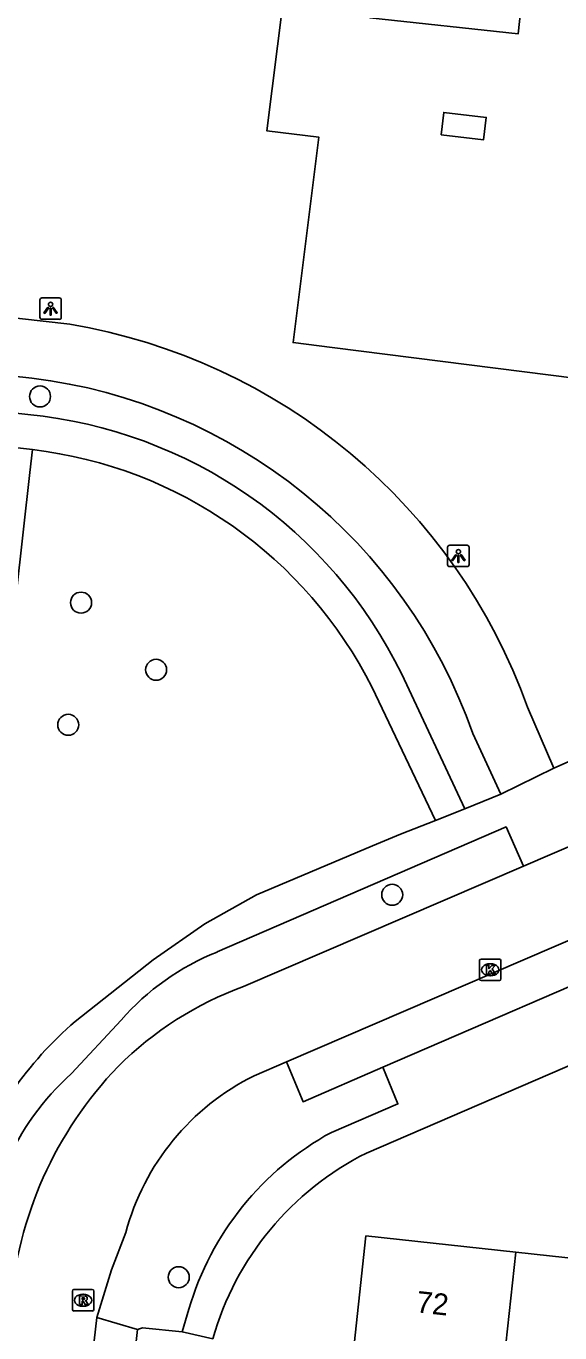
# Model space of a CAD drawing. Extents: x 162026 to 163499, y 387297 to 388169.
# Drawn here: x 162177.7 to 162202.5, y 387793.2 to 387854 of the extents above; entities that cross this region are included whole.
import ezdxf

# ---------------------------------------------------------------- set-up
doc = ezdxf.new("R2010")
doc.units = 0
for name, color, linetype in [('IMGEO_Boom', 7, 'Continuous'), ('IMGEO_Fietspad_gesloten', 7, 'Continuous'), ('IMGEO_Kolk', 7, 'Continuous'), ('IMGEO_Lichtpunt', 7, 'Continuous'), ('IMGEO_Loofbos', 7, 'Continuous'), ('IMGEO_Pand', 7, 'Continuous'), ('IMGEO_Pand_nummerreeks', 7, 'Continuous'), ('IMGEO_Parkeervlak_open', 7, 'Continuous'), ('IMGEO_Rijbaan_lokaal_open', 7, 'Continuous'), ('IMGEO_Rioolput', 7, 'Continuous'), ('IMGEO_Voetpad_open', 7, 'Continuous')]:
    doc.layers.add(name, color=color, linetype=linetype)

msp = doc.modelspace()

# ---------------------------------------------------------------- linework, layer by layer
at = {"layer": 'IMGEO_Boom'}
for centre in [(162178.326, 387836.8), (162180.234, 387827.201), (162183.726, 387824.075), (162179.638, 387821.513), (162194.71, 387813.598), (162184.778, 387795.79)]:
    msp.add_circle(centre, 0.489, dxfattribs=at)
at = {"layer": 'IMGEO_Fietspad_gesloten'}
for points in [[(162177.938, 387837.659), (162144.47, 387841.312)], [(162179.708, 387840.17), (162175.011, 387840.691)], [(162202.235, 387819.498), (162201.008, 387822.336)], [(162199.757, 387818.285), (162198.454, 387821.109)], [(162199.757, 387818.285), (162202.235, 387819.498)]]:
    msp.add_lwpolyline(points, dxfattribs=at)
for centre, radius, start, end in [((162175.123, 387813.057), 27.498, 19.72143, 80.40124), ((162174.885, 387812.883), 24.963, 19.23986, 82.97477)]:
    msp.add_arc(centre, radius, start, end, dxfattribs=at)
at = {"layer": 'IMGEO_Kolk'}
for p, q in [((162198.768, 387809.68), (162198.768, 387810.532)), ((162198.843, 387810.606), (162199.695, 387810.606)), ((162199.256, 387810.386), (162199.281, 387810.386)), ((162199.769, 387810.532), (162199.769, 387809.68)), ((162199.279, 387809.826), (162199.254, 387809.826)), ((162199.695, 387809.606), (162198.843, 387809.606))]:
    msp.add_line(p, q, dxfattribs=at)
for points in [[(162198.768, 387809.68), (162198.768, 387810.532)], [(162198.843, 387810.606), (162199.695, 387810.606)], [(162199.089, 387810.306), (162199.212, 387810.306), (162199.212, 387810.155), (162199.342, 387810.306), (162199.506, 387810.306), (162199.36, 387810.155), (162199.513, 387809.906), (162199.361, 387809.906), (162199.276, 387810.07), (162199.212, 387810.003), (162199.212, 387809.906), (162199.089, 387809.906), (162199.089, 387810.306)], [(162199.769, 387810.532), (162199.769, 387809.68)], [(162199.695, 387809.606), (162198.843, 387809.606)]]:
    msp.add_lwpolyline(points, dxfattribs=at)
for centre, start, end in [((162198.845, 387810.53), 91.55205, 178.44795), ((162198.845, 387810.53), 91.55205, 178.44795), ((162199.693, 387810.53), 1.55205, 88.44795), ((162199.693, 387810.53), 1.55205, 88.44795), ((162198.845, 387809.682), 181.55205, 268.44795), ((162198.845, 387809.682), 181.55205, 268.44795), ((162199.693, 387809.682), 271.55205, 358.44795), ((162199.693, 387809.682), 271.55205, 358.44795)]:
    msp.add_arc(centre, 0.0765, start, end, dxfattribs=at)
for centre, major_axis, ratio, start_param, end_param in [((162199.255, 387810.106), (-0.387, 0.002), 0.722429, 4.712389, 7.853982), ((162199.28, 387810.106), (-0.39, 0.002), 0.717154, 1.570796, 4.712389)]:
    msp.add_ellipse(centre, major_axis=major_axis, ratio=ratio, start_param=start_param, end_param=end_param, dxfattribs=at)
at = {"layer": 'IMGEO_Lichtpunt'}
for p, q in [((162179.222, 387841.389), (162178.414, 387841.389)), ((162179.222, 387841.389), (162178.414, 387841.389)), ((162178.32, 387841.294), (162178.32, 387840.487)), ((162178.32, 387841.294), (162178.32, 387840.487)), ((162179.316, 387840.487), (162179.316, 387841.294)), ((162179.316, 387840.487), (162179.316, 387841.294)), ((162178.414, 387840.393), (162179.222, 387840.393)), ((162178.414, 387840.393), (162179.222, 387840.393)), ((162197.29, 387829.778), (162197.29, 387828.971)), ((162197.29, 387829.778), (162197.29, 387828.971)), ((162198.192, 387829.873), (162197.384, 387829.873)), ((162198.192, 387829.873), (162197.384, 387829.873)), ((162198.286, 387828.971), (162198.286, 387829.778)), ((162198.286, 387828.971), (162198.286, 387829.778)), ((162197.384, 387828.877), (162198.192, 387828.877)), ((162197.384, 387828.877), (162198.192, 387828.877))]:
    msp.add_line(p, q, dxfattribs=at)
for points in [[(162178.694, 387840.958), (162178.733, 387840.93), (162178.545, 387840.668), (162178.507, 387840.695), (162178.694, 387840.958)], [(162178.796, 387840.91), (162178.843, 387840.91), (162178.843, 387840.588), (162178.796, 387840.588), (162178.796, 387840.91)], [(162178.906, 387840.93), (162178.944, 387840.957), (162179.131, 387840.695), (162179.092, 387840.667), (162178.906, 387840.93)], [(162197.664, 387829.442), (162197.703, 387829.414), (162197.515, 387829.152), (162197.477, 387829.179), (162197.664, 387829.442)], [(162197.766, 387829.394), (162197.813, 387829.394), (162197.813, 387829.072), (162197.766, 387829.072), (162197.766, 387829.394)], [(162197.876, 387829.414), (162197.914, 387829.441), (162198.101, 387829.179), (162198.062, 387829.151), (162197.876, 387829.414)]]:
    msp.add_lwpolyline(points, dxfattribs=at)
for centre in [(162178.819, 387841.092), (162197.789, 387829.576)]:
    msp.add_circle(centre, 0.0994, dxfattribs=at)
for centre, start, end in [((162178.414, 387841.294), 90, 180), ((162178.414, 387841.294), 90, 180), ((162179.222, 387841.294), 0, 90), ((162179.222, 387841.294), 0, 90), ((162178.414, 387840.487), 180, 270), ((162178.414, 387840.487), 180, 270), ((162179.222, 387840.487), 270, 0), ((162179.222, 387840.487), 270, 360), ((162197.384, 387829.778), 90, 180), ((162197.384, 387829.778), 90, 180), ((162198.192, 387829.778), 0, 90), ((162198.192, 387829.778), 0, 90), ((162197.384, 387828.971), 180, 270), ((162197.384, 387828.971), 180, 270), ((162198.192, 387828.971), 270, 0), ((162198.192, 387828.971), 270, 360)]:
    msp.add_arc(centre, 0.0946, start, end, dxfattribs=at)
at = {"layer": 'IMGEO_Loofbos'}
msp.add_lwpolyline([(162184.551, 387875.63), (162182.846, 387859.915), (162190.113, 387859.038), (162188.873, 387849.177), (162191.3, 387848.871), (162190.097, 387839.307), (162191.913, 387839.079), (162203.311, 387837.645)], dxfattribs=at)
at = {"layer": 'IMGEO_Pand'}
for points in [[(162201.035, 387857.999), (162200.573, 387853.691), (162193.673, 387854.43), (162194.115, 387858.555), (162194.134, 387858.736)], [(162196.985, 387848.985), (162198.959, 387848.752), (162199.082, 387849.793), (162197.108, 387850.026), (162196.985, 387848.985)], [(162173.885, 387834.782), (162177.973, 387834.328)], [(162177.973, 387834.328), (162177.854, 387833.262), (162176.897, 387824.645)], [(162199.373, 387786.958), (162192.725, 387787.692), (162192.056, 387785.942), (162188.887, 387787.149), (162190.586, 387791.589), (162192.793, 387791.349), (162193.484, 387797.711), (162200.458, 387796.953)], [(162199.373, 387786.958), (162200.458, 387796.953)], [(162200.458, 387796.953), (162207.432, 387796.196), (162206.671, 387789.191), (162209.336, 387788.901)]]:
    msp.add_lwpolyline(points, dxfattribs=at)
at = {"layer": 'IMGEO_Parkeervlak_open'}
for points in [[(162189.791, 387805.824), (162190.563, 387803.958), (162194.28, 387805.571)], [(162182.857, 387793.357), (162180.964, 387793.918)]]:
    msp.add_lwpolyline(points, dxfattribs=at)
at = {"layer": 'IMGEO_Rijbaan_lokaal_open'}
for points in [[(162203.592, 387816.121), (162200.815, 387814.926)], [(162200.815, 387814.926), (162187.797, 387809.321)], [(162189.791, 387805.824), (162206.331, 387812.946)], [(162188.282, 387805.175), (162189.791, 387805.824)], [(162180.964, 387793.918), (162181.652, 387796.139), (162182.316, 387797.88)], [(162180.964, 387793.918), (162178.729, 387774.397)]]:
    msp.add_lwpolyline(points, dxfattribs=at)
for centre, radius, start, end in [((162193.17, 387794.439), 15.822, 109.85106, 135.1332), ((162195.063, 387793.031), 18.161, 136.19827, 175.6852), ((162193.433, 387794.875), 11.516, 116.5704, 164.8756)]:
    msp.add_arc(centre, radius, start, end, dxfattribs=at)
at = {"layer": 'IMGEO_Rioolput'}
for p, q in [((162179.83, 387794.292), (162179.83, 387795.144)), ((162179.905, 387795.218), (162180.757, 387795.218)), ((162180.831, 387795.144), (162180.831, 387794.292)), ((162180.318, 387794.998), (162180.343, 387794.998)), ((162180.757, 387794.218), (162179.905, 387794.218)), ((162180.341, 387794.438), (162180.316, 387794.438))]:
    msp.add_line(p, q, dxfattribs=at)
for points in [[(162179.83, 387794.292), (162179.83, 387795.144)], [(162179.905, 387795.218), (162180.757, 387795.218)], [(162180.831, 387795.144), (162180.831, 387794.292)], [(162180.419, 387794.916), (162180.167, 387794.918), (162180.167, 387794.518)], [(162180.167, 387794.518), (162180.291, 387794.518), (162180.291, 387794.68), (162180.302, 387794.68)], [(162180.345, 387794.837), (162180.291, 387794.837), (162180.291, 387794.756)], [(162180.291, 387794.756), (162180.343, 387794.756)], [(162180.349, 387794.651), (162180.42, 387794.518), (162180.56, 387794.518), (162180.495, 387794.644)], [(162180.757, 387794.218), (162179.905, 387794.218)]]:
    msp.add_lwpolyline(points, dxfattribs=at)
for centre, radius, start, end in [((162179.907, 387795.142), 0.0765, 91.55205, 178.44795), ((162179.907, 387795.142), 0.0765, 91.55205, 178.44795), ((162180.755, 387795.142), 0.0765, 1.55205, 88.44795), ((162180.755, 387795.142), 0.0765, 1.55205, 88.44795), ((162180.301, 387794.627), 0.0533, 26.02933, 88.69889), ((162180.327, 387794.945), 0.19, 274.7715, 282.96867), ((162180.351, 387794.741), 0.0964, 77.00612, 93.18647), ((162180.365, 387794.798), 0.0378, 276.66336, 79.67722), ((162180.418, 387794.806), 0.109, 350.36119, 89.41601), ((162180.416, 387794.806), 0.112, 277.58423, 350.98172), ((162180.4, 387794.591), 0.108, 29.51342, 73.79051), ((162179.907, 387794.294), 0.0765, 181.55205, 268.44795), ((162179.907, 387794.294), 0.0765, 181.55205, 268.44795), ((162180.755, 387794.294), 0.0765, 271.55205, 358.44795), ((162180.755, 387794.294), 0.0765, 271.55205, 358.44795)]:
    msp.add_arc(centre, radius, start, end, dxfattribs=at)
for centre, major_axis, ratio, start_param, end_param in [((162180.317, 387794.718), (-0.387, 0.002), 0.722429, 4.712389, 7.853982), ((162180.342, 387794.718), (-0.39, 0.002), 0.717154, 1.570796, 4.712389)]:
    msp.add_ellipse(centre, major_axis=major_axis, ratio=ratio, start_param=start_param, end_param=end_param, dxfattribs=at)
at = {"layer": 'IMGEO_Voetpad_open'}
for points in [[(162144.47, 387841.312), (162144.349, 387839.619), (162177.764, 387835.959)], [(162214.54, 387824.935), (162202.235, 387819.498)], [(162195.153, 387823.865), (162198.087, 387817.607)], [(162193.78, 387823.243), (162196.718, 387817.061)], [(162234.558, 387819.299), (162220.399, 387813.185), (162193.512, 387801.574)], [(162198.087, 387817.607), (162199.757, 387818.285)], [(162196.718, 387817.061), (162198.087, 387817.607)], [(162196.718, 387817.061), (162195.098, 387816.416), (162193.797, 387815.873), (162188.39, 387813.592), (162185.998, 387812.245), (162183.587, 387810.567), (162179.961, 387807.703)], [(162186.562, 387810.934), (162200.009, 387816.755), (162200.815, 387814.926)], [(162194.28, 387805.571), (162207.126, 387811.125)], [(162179.786, 387805.274), (162182.095, 387807.76)], [(162191.881, 387802.535), (162194.972, 387803.863), (162194.28, 387805.571)], [(162184.931, 387793.25), (162185.254, 387794.309)], [(162180.732, 387774.305), (162182.252, 387787.828), (162182.857, 387793.357)], [(162184.931, 387793.25), (162183.098, 387793.438), (162182.857, 387793.357)], [(162186.364, 387792.928), (162184.931, 387793.25)]]:
    msp.add_lwpolyline(points, dxfattribs=at)
for centre, radius, start, end in [((162175.651, 387814.372), 21.69, 25.9544, 84.40859), ((162175.575, 387814.095), 20.374, 26.67804, 83.24018), ((162190.905, 387800.092), 11.679, 111.82766, 138.96327), ((162191.407, 387794.495), 17.477, 130.91043, 145.26918), ((162188.185, 387795.99), 12.519, 132.13594, 180.27633), ((162198.501, 387790.42), 13.806, 118.65162, 163.6374), ((162199.766, 387789.126), 13.931, 116.67514, 164.16101)]:
    msp.add_arc(centre, radius, start, end, dxfattribs=at)

# ---------------------------------------------------------------- texts
at = {"layer": 'IMGEO_Pand_nummerreeks'}
msp.add_text('72', height=1, rotation=353.80096, dxfattribs=at).set_placement((162195.793, 387794.161))

doc.saveas('drawing.dxf')
